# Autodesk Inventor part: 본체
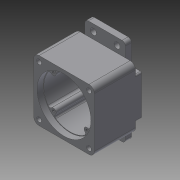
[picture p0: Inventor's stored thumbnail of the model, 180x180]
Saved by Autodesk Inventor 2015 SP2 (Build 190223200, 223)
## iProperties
Created: 2015-06
Part Number: 본체
Material: 일반
Document SubType Name: Modeling
Designer: AMC
Density: 1 g/cm^3
Appearance: 기본값
Author: AMC
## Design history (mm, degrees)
sketch "스케치1"
  geometry: L1 (-45, 45)-(45, 45); L2 (45, 45)-(45, -45); L3 (45, -45)-(-45, -45); L4 (-45, -45)-(-45, 45); 3 further points
  constraints: 8 end point, 2 midpoint, 2 parallel, 1 horizontal, 1 horizontal alignment, 1 perpendicular, 1 vertical alignment
  dimensions: "d0" = 90 distance of L2.end L3.end; "d1" = 90 distance of L1.end L2.end
extrude "돌출1" new body sketch "스케치1" distance "d2" = 61; taper "d3" = 0 deg
sketch "스케치2"
  geometry: C1 r 40 at (0, 0); 1 further point
  constraints: 1 centre point, 1 coincident
  dimensions: "d4" = 80 diameter of C1
extrude "돌출2" cut sketch "스케치2" distance "d5" = 9; taper "d6" = 0 deg
sketch "스케치3"
  geometry: C1 r 39 at (0, 0); 1 further point
  constraints: 1 centre point, 1 coincident
  dimensions: "d7" = 78 diameter of C1
extrude "돌출3" cut sketch "스케치3" distance "d8" = 61; taper "d9" = 0 deg
sketch "스케치5"
  geometry: L1 (-30, -65)-(30, -65); L2 (30, -65)-(30, 65); L3 (30, 65)-(-30, 65); L4 (-30, 65)-(-30, -65); L5 (-45, 45)-(-45, -45) reference; L6 (45, 45)-(45, -45) reference; L7 (-45, -30)-(45, -30); L8 (45, -30)-(45, 30); L9 (45, 30)-(-45, 30); L10 (-45, 30)-(-45, -30); 5 further points
  constraints: 16 end point, 4 midpoint, 4 parallel, 2 horizontal, 2 horizontal alignment, 2 perpendicular, 2 point on line, 1 vertical alignment
  dimensions: "d24" = 130 distance between parallel lines of L3 L1; "d25" = 60 distance of L1.start L1.end; "d28" = 60 distance between parallel lines of L9 L7
extrude "돌출4" join sketch "스케치5" distance "d26" = 9; taper "d27" = 0 deg
sketch "스케치7"
  geometry: C1 r 25 at (-11, 0); 1 further point
  constraints: 1 centre point
  dimensions: "d31" = 50 diameter of C1; "d32" = 11 distance of point (0, 0) C1.centre
extrude "돌출5" join sketch "스케치7" distance "d33" = 7; taper "d34" = 0 deg
sketch "스케치13"
  geometry: L1 (45, 45)-(45, -45) reference; L2 (45, -45)-(-45, -45) reference; L3 (-45, -45)-(-45, 45) reference; L4 (-45, 45)-(45, 45) reference; L5 (0, 0)-(-24.749, 24.749); L6 (0, 0)-(-33.462, 0); L7 (-21.763, 27.411)-(-24.429, 30.401); L8 (-27.411, 21.763)-(-30.401, 24.429); C1 r 40 at (0, 0) reference; C2 r 39 at (0, 0) reference; A1 r 39 centre (0, 0) between (-24.429, 30.401) and (-30.401, 24.429) reference; A2 r 4 centre (-24.749, 24.749) between (-27.411, 21.763) and (-21.763, 27.411); A3 r 35 centre (0, 0) between (-21.763, 27.411) and (-27.411, 21.763); 1 further point
  constraints: 8 end point, 6 point on circle, 2 centre point, 2 coincident, 2 tangent, 1 horizontal
  dimensions: "d56" = 35 distance of L5.start L5.end; "d57" = 45 deg angle of L6 L5; "d58" = 8 diameter of A2; "d59" = 70 diameter of A3
extrude "돌출8" join sketch "스케치13" stored distance "d60" = 20; taper "d61" = 0 deg
fillet "모깎기2" dims "d62" = 3.5
sketch "스케치17"
  geometry: A1 r 20.5 centre (11, 0) between (-8.117, -7.402) and (-8.117, 7.402); A2 r 14 centre (-20, 0) between (-8.117, 7.402) and (-8.117, -7.402); 1 further point
  constraints: 4 point on circle, 2 centre point, 2 horizontal alignment
  dimensions: "d73" = 41 diameter of A1; "d74" = 28 diameter of A2; "d75" = 11 distance of point (0, 0) A1.centre; "d76" = 20 distance of point (0, 0) A2.centre
extrude "돌출10" join sketch "스케치17" distance "d77" = 7; taper "d78" = 0 deg
sketch "스케치18"
  geometry: L1 (-40, 61)-(-40, 52) reference; L2 (-40, 52)-(-39, 52) reference; L3 (-39, 52)-(-39, 0) reference; L4 (-39, 0)-(-31.5, 0) reference; L5 (-31.5, 0)-(-31.5, 7) reference; L6 (-31.5, 7)-(34, 7) reference; L7 (34, 7)-(34, 0) reference; L8 (34, 0)-(39, 0) reference; L9 (39, 0)-(39, 52) reference; L10 (39, 52)-(40, 52) reference; L11 (40, 52)-(40, 61) reference; L12 (40, 61)-(45, 61) reference; L13 (45, 61)-(45, -9) reference; L14 (45, -9)-(14, -9) reference; L15 (14, -9)-(14, -16) reference; L16 (14, -16)-(-36, -16) reference; L17 (-36, -16)-(-36, -9) reference; L18 (-36, -9)-(-45, -9) reference; L19 (-45, -9)-(-45, 61) reference; L20 (-45, 61)-(-40, 61) reference; L21 (-36, -16)-(14, -16) reference; L22 (-11, -16)-(-11, 7); L23 (-11, -16)-(-27, -16); L24 (-27, -16)-(-27, -8); L25 (-27, -8)-(-23.5, -8); L26 (-23.5, -8)-(-23.5, -3); L27 (-28.5, 7)-(-11, 7); L28 (8.117, 7)-(-31.5, 7) reference; L29 (-23.5, -3)-(-28.5, -3); L30 (-28.5, -3)-(-28.5, 7); 1 further point
  constraints: 16 end point, 4 perpendicular, 3 point on line, 1 collinear, 1 horizontal, 1 midpoint, 1 vertical
  dimensions: "d79" = 11 distance from line of point (0, 0) L22; "d80" = 32 diameter of L24 L22; "d81" = 8 distance of L23.end L24.end; "d82" = 10 distance of L29.end L27.start; "d83" = 25 diameter of L26 L22; "d84" = 35 diameter of L30 L22
revolve "회전2" sketch "스케치18" stored, may be unused: angle "d85" = 90 deg
sketch "스케치19"
  geometry: L1 (40, 52)-(40, 61) reference; L2 (40, 61)-(45, 61) reference; L3 (45, 61)-(45, -9) reference; L4 (45, -9)-(14, -9) reference; L5 (14, -9)-(14, -16) reference; L6 (14, -16)-(5, -16) reference; L7 (5, -16)-(5, -8) reference; L8 (5, -8)-(1.5, -8) reference; L9 (1.5, -8)-(1.5, -3) reference; L10 (1.5, -3)-(6.5, -3) reference; L11 (6.5, -3)-(6.5, 7) reference; L12 (6.5, 7)-(34, 7) reference; L13 (34, 7)-(34, 0) reference; L14 (34, 0)-(39, 0) reference; L15 (39, 0)-(39, 52) reference; L16 (39, 52)-(40, 52) reference; L17 (-40, 61)-(-40, 52) reference; L18 (-40, 52)-(-39, 52) reference; L19 (-39, 52)-(-39, 0) reference; L20 (-39, 0)-(-31.5, 0) reference; L21 (-31.5, 0)-(-31.5, 7) reference; L22 (-31.5, 7)-(-28.5, 7) reference; L23 (-28.5, 7)-(-28.5, -3) reference; L24 (-28.5, -3)-(-23.5, -3) reference; L25 (-23.5, -3)-(-23.5, -8) reference; L26 (-23.5, -8)-(-27, -8) reference; L27 (-27, -8)-(-27, -16) reference; L28 (-27, -16)-(-36, -16) reference; L29 (-36, -16)-(-36, -9) reference; L30 (-36, -9)-(-45, -9) reference; L31 (-45, -9)-(-45, 61) reference; L32 (-45, 61)-(-40, 61) reference; L33 (-30, -9)-(30, -9) reference; L34 (20, 0)-(20, 7); L35 (20, 0)-(9, 0); L36 (9, 0)-(9, 7); L37 (10.5, 0)-(10.5, 0); 1 further point
  constraints: 8 end point, 4 perpendicular, 3 point on line
  dimensions: "d86" = 20 horizontal distance of point (0, 0) L34.end; "d87" = 22 diameter of L36 L34; "d88" = 7 distance of L35.end L36.end; "d89" = 19 diameter of L37 L34
revolve "회전3" sketch "스케치19" stored, may be unused: angle "d92" = 90 deg
sketch "스케치20"
  geometry: L1 (40, 52)-(40, 61) reference; L2 (40, 61)-(45, 61) reference; L3 (45, 61)-(45, -9) reference; L4 (45, -9)-(14, -9) reference; L5 (14, -9)-(14, -16) reference; L6 (14, -16)-(5, -16) reference; L7 (5, -16)-(5, -8) reference; L8 (5, -8)-(1.5, -8) reference; L9 (1.5, -8)-(1.5, -3) reference; L10 (1.5, -3)-(6.5, -3) reference; L11 (6.5, -3)-(6.5, 7) reference; L12 (6.5, 7)-(9, 7) reference; L13 (9, 7)-(9, 0) reference; L14 (9, 0)-(31, 0) reference; L15 (31, 0)-(31, 7) reference; L16 (31, 7)-(34, 7) reference; L17 (34, 7)-(34, 0) reference; L18 (34, 0)-(39, 0) reference; L19 (39, 0)-(39, 52) reference; L20 (39, 52)-(40, 52) reference; L21 (-40, 61)-(-40, 52) reference; L22 (-40, 52)-(-39, 52) reference; L23 (-39, 52)-(-39, 0) reference; L24 (-39, 0)-(-31.5, 0) reference; L25 (-31.5, 0)-(-31.5, 7) reference; L26 (-31.5, 7)-(-28.5, 7) reference; L27 (-28.5, 7)-(-28.5, -3) reference; L28 (-28.5, -3)-(-23.5, -3) reference; L29 (-23.5, -3)-(-23.5, -8) reference; L30 (-23.5, -8)-(-27, -8) reference; L31 (-27, -8)-(-27, -16) reference; L32 (-27, -16)-(-36, -16) reference; L33 (-36, -16)-(-36, -9) reference; L34 (-36, -9)-(-45, -9) reference; L35 (-45, -9)-(-45, 61) reference; L36 (-45, 61)-(-40, 61) reference; L37 (9, 0)-(31, 0) reference; L38 (20, 0)-(20, -1); L39 (20, -1)-(10.5, -1); L40 (10.5, -1)-(10.5, 0); 1 further point
  constraints: 6 end point, 1 horizontal, 1 midpoint, 1 perpendicular, 1 point on line, 1 vertical
  dimensions: "d93" = 19 diameter of L40 L38; "d94" = 1 distance between parallel lines of L14 L39
revolve "회전4" sketch "스케치20" stored, may be unused: angle "d95" = 90 deg
fillet "모깎기3" dims "d96" = 1
fillet "모깎기4" dims "d97" = 2
fillet "모깎기5" dims "d98" = 5
fillet "모깎기6" dims "d99" = 2
fillet "모깎기8" dims "d101" = 8
fillet "모깎기9" dims "d102" = 2
fillet "모깎기10" dims "d103" = 5
sketch "스케치21"
  geometry: L1 (45, 37)-(45, -37) reference; L2 (37, -45)-(-37, -45) reference; L3 (-45, -37)-(-45, 37) reference; L4 (-37, 45)-(37, 45) reference; C1 r 40 at (0, 0) reference; C2 r 3.5 at (-37, 37); A1 r 8 centre (37, 37) between (45, 37) and (37, 45) reference; A2 r 8 centre (37, -37) between (37, -45) and (45, -37) reference; A3 r 8 centre (-37, -37) between (-45, -37) and (-37, -45) reference; A4 r 8 centre (-37, 37) between (-37, 45) and (-45, 37) reference; 1 further point
  constraints: 1 centre point, 1 coincident
  dimensions: "d105" = 7 diameter of C2
extrude "돌출11" cut sketch "스케치21" stored distance "d106" = 10; taper "d107" = 0 deg
sketch "스케치22"
  geometry: L1 (45, 37)-(45, -37) reference; L2 (37, -45)-(-37, -45) reference; L3 (-45, -37)-(-45, 37) reference; L4 (-37, 45)-(37, 45) reference; L5 (-30, -45)-(-30, -60) reference; L6 (-30, -45)-(30, -45) reference; L7 (30, -60)-(30, -45) reference; L8 (-25, -65)-(25, -65) reference; L9 (30, 45)-(30, 60) reference; L10 (30, 45)-(-30, 45) reference; L11 (-30, 60)-(-30, 45) reference; L12 (25, 65)-(-25, 65) reference; L13 (-17.5, -55)-(17.5, -55); C1 r 3.5 at (37, 37) reference; C2 r 3.5 at (37, -37) reference; C3 r 3.5 at (-37, -37) reference; C4 r 3.5 at (-37, 37) reference; C5 r 40 at (0, 0) reference; C6 r 4.5 at (-17.5, -55); C7 r 4.5 at (17.5, -55); A1 r 8 centre (37, 37) between (45, 37) and (37, 45) reference; A2 r 8 centre (37, -37) between (37, -45) and (45, -37) reference; A3 r 8 centre (-37, -37) between (-45, -37) and (-37, -45) reference; A4 r 8 centre (-37, 37) between (-37, 45) and (-45, 37) reference; A5 r 5 centre (-25, -60) between (-30, -60) and (-25, -65) reference; A6 r 5 centre (25, -60) between (25, -65) and (30, -60) reference; A7 r 5 centre (25, 60) between (30, 60) and (25, 65) reference; A8 r 5 centre (-25, 60) between (-25, 65) and (-30, 60) reference; 2 further points
  constraints: 2 centre point, 2 end point, 1 horizontal, 1 horizontal alignment, 1 midpoint, 1 vertical alignment
  dimensions: "d111" = 9 diameter of C6; "d112" = 9 diameter of C7; "d113" = 35 distance of L13.end L13.start; "d114" = 55 vertical distance of point (0, 0) L13.start
extrude "돌출12" cut sketch "스케치22" stored distance "d115" = 10; taper "d116" = 0 deg
node "작업 평면2"
sketch "스케치23"
  geometry: A1 r 6 centre (-24.749, -24.749) between (-20.271, -28.742) and (-28.742, -20.271) reference; 2 further points
  constraints: 1 coincident
hole "구멍1" sketch "스케치23" at (-24.749, -24.749) diameter "d117" = 3.242; stored, may be unused: countersink angle "d121" = 90 deg, drill point angle "d123" = 118 deg; dims "d118" = 12, "d119" = 4, "d120" = 2, "d122" = 15
chamfer "모따기1" distance "d127" = 1; stored, may be unused: second distance "d128" = 2, angle "d129" = 45 deg
fillet "모깎기11" dims "d130" = 0.3
node "솔리드1"
pattern_circular "원형 패턴1" dims angle "d64" = 360 deg
pattern_circular "원형 패턴2" dims angle "d109" = 360 deg
mirror "대칭1"
pattern_circular "원형 패턴3" dims angle "d125" = 360 deg
node "투영된 루프1"
node "투영된 루프2"
node "투영된 루프3"
node "투영된 루프4"
node "절단 모서리 투영7"
node "절단 모서리 투영11"
node "절단 모서리 투영12"
node "절단 모서리 투영13"
other parameters: "d66" = 28, "d67" = 41
